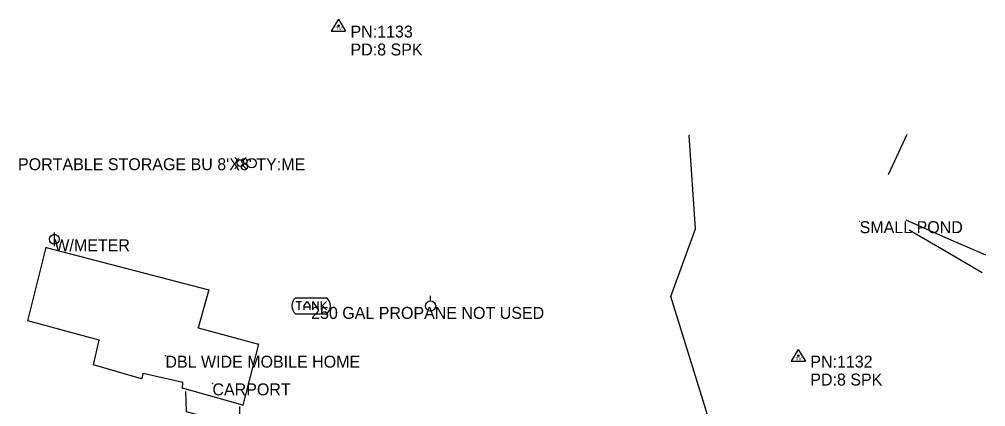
# Model space of a CAD drawing. Extents: x 878399 to 889864, y 1564003 to 1567413.
# Drawn here: x 886066 to 886469.7, y 1564707.5 to 1564869.4 of the extents above; entities that cross this region are included whole.
import ezdxf

# ---------------------------------------------------------------- set-up
doc = ezdxf.new("R2010")
doc.units = 0
for name, color, linetype in [('S_BUILDING', 7, 'Continuous'), ('S_DITCHLINE', 7, 'Continuous'), ('S_EDGE_BITUMINOUS', 7, 'Continuous'), ('S_FENCE', 7, 'Continuous'), ('S_MSC_PT_SYM', 7, 'Continuous'), ('S_SECONDARY_CTL', 7, 'Continuous'), ('S_SECONDARY_CTL_ANNOT', 7, 'Continuous'), ('S_STR_PT_SYM', 7, 'Continuous'), ('S_SURVEY_TEXT_ANNOT', 7, 'Continuous'), ('S_TANK', 7, 'Continuous'), ('S_TANK_ANNOT', 7, 'Continuous'), ('S_UTILITY_POLE', 7, 'Continuous'), ('S_UTILITY_POLE_ANNOT', 7, 'Continuous')]:
    doc.layers.add(name, color=color, linetype=linetype)

msp = doc.modelspace()

# ---------------------------------------------------------------- linework, layer by layer
at = {"layer": 'S_BUILDING'}
for p, q in [((886069.58, 1564743.36), (886077.3, 1564774.11)), ((886077.3, 1564774.11), (886145.13, 1564756.32)), ((886145.13, 1564756.32), (886140.72, 1564740.53)), ((886099.45, 1564735.27), (886069.58, 1564743.36)), ((886140.72, 1564740.53), (886165.87, 1564733.62)), ((886097.06, 1564725.06), (886099.45, 1564735.27)), ((886165.87, 1564733.62), (886159.4, 1564708.12)), ((886117.05, 1564719.16), (886097.06, 1564725.06)), ((886117.77, 1564721.44), (886117.05, 1564719.16)), ((886134.3, 1564717.64), (886117.77, 1564721.44)), ((886134.22, 1564715.25), (886134.3, 1564717.64)), ((886159.4, 1564708.12), (886134.22, 1564715.25))]:
    msp.add_line(p, q, dxfattribs=at)
at = {"layer": 'S_DITCHLINE'}
for points in [[(886436.81, 1564821.26), (886428.95, 1564804.48)], [(886469.69, 1564770.81), (886453.05, 1564778.16), (886436.42, 1564785.51)], [(886468.22, 1564763.5), (886453.01, 1564772.37), (886437.79, 1564781.25)]]:
    msp.add_lwpolyline(points, dxfattribs=at)
at = {"layer": 'S_EDGE_BITUMINOUS'}
msp.add_lwpolyline([(886135.38, 1564713.85), (886135.68, 1564705.53), (886158.05, 1564699.54), (886158.15, 1564707.53)], dxfattribs=at)
at = {"layer": 'S_FENCE'}
for p, q in [((886348.44, 1564781.84), (886345.77, 1564820.82)), ((886338.23, 1564753.54), (886348.44, 1564781.84)), ((886360.27, 1564682.48), (886338.23, 1564753.54))]:
    msp.add_line(p, q, dxfattribs=at)
at = {"layer": 'S_MSC_PT_SYM'}
for points in [[(886345.77, 1564820.82), (886345.77, 1564820.87), (886345.77, 1564820.82), (886345.72, 1564820.82), (886345.77, 1564820.82), (886345.77, 1564820.77), (886345.77, 1564820.82), (886345.82, 1564820.82)], [(886348.44, 1564781.84), (886348.44, 1564781.89), (886348.44, 1564781.84), (886348.39, 1564781.84), (886348.44, 1564781.84), (886348.44, 1564781.79), (886348.44, 1564781.84), (886348.49, 1564781.84)], [(886417.03, 1564785.05), (886417.03, 1564785.1), (886417.03, 1564785.05), (886416.98, 1564785.05), (886417.03, 1564785.05), (886417.03, 1564785), (886417.03, 1564785.05), (886417.08, 1564785.05)], [(886338.23, 1564753.54), (886338.23, 1564753.59), (886338.23, 1564753.54), (886338.18, 1564753.54), (886338.23, 1564753.54), (886338.23, 1564753.49), (886338.23, 1564753.54), (886338.28, 1564753.54)], [(886127.05, 1564728.83), (886127.05, 1564728.88), (886127.05, 1564728.83), (886127, 1564728.83), (886127.05, 1564728.83), (886127.05, 1564728.78), (886127.05, 1564728.83), (886127.1, 1564728.83)], [(886146.69, 1564717.25), (886146.69, 1564717.3), (886146.69, 1564717.25), (886146.64, 1564717.25), (886146.69, 1564717.25), (886146.69, 1564717.2), (886146.69, 1564717.25), (886146.74, 1564717.25)]]:
    msp.add_lwpolyline(points, dxfattribs=at)
at = {"layer": 'S_SECONDARY_CTL'}
for p, q in [((886199.37, 1564869.43), (886196.36, 1564864.48)), ((886199.37, 1564869.43), (886202.31, 1564864.48)), ((886196.36, 1564864.48), (886202.31, 1564864.48)), ((886391.43, 1564731.47), (886388.42, 1564726.52)), ((886391.43, 1564731.47), (886394.38, 1564726.52)), ((886388.42, 1564726.52), (886394.38, 1564726.52))]:
    msp.add_line(p, q, dxfattribs=at)
for centre, radius in [((886199.37, 1564866.82), 0.311), ((886199.37, 1564866.82), 0.183), ((886199.37, 1564866.82), 0.103), ((886391.43, 1564728.86), 0.311), ((886391.43, 1564728.86), 0.183), ((886391.43, 1564728.86), 0.103)]:
    msp.add_circle(centre, radius, dxfattribs=at)
at = {"layer": 'S_STR_PT_SYM'}
for points in [[(886077.3, 1564774.11), (886077.3, 1564774.16), (886077.3, 1564774.11), (886077.25, 1564774.11), (886077.3, 1564774.11), (886077.3, 1564774.06), (886077.3, 1564774.11), (886077.35, 1564774.11)], [(886145.13, 1564756.32), (886145.13, 1564756.37), (886145.13, 1564756.32), (886145.08, 1564756.32), (886145.13, 1564756.32), (886145.13, 1564756.27), (886145.13, 1564756.32), (886145.18, 1564756.32)], [(886069.58, 1564743.36), (886069.58, 1564743.41), (886069.58, 1564743.36), (886069.53, 1564743.36), (886069.58, 1564743.36), (886069.58, 1564743.31), (886069.58, 1564743.36), (886069.63, 1564743.36)], [(886140.72, 1564740.53), (886140.72, 1564740.58), (886140.72, 1564740.53), (886140.67, 1564740.53), (886140.72, 1564740.53), (886140.72, 1564740.48), (886140.72, 1564740.53), (886140.77, 1564740.53)], [(886099.45, 1564735.27), (886099.45, 1564735.32), (886099.45, 1564735.27), (886099.4, 1564735.27), (886099.45, 1564735.27), (886099.45, 1564735.22), (886099.45, 1564735.27), (886099.5, 1564735.27)], [(886165.87, 1564733.62), (886165.87, 1564733.67), (886165.87, 1564733.62), (886165.82, 1564733.62), (886165.87, 1564733.62), (886165.87, 1564733.57), (886165.87, 1564733.62), (886165.92, 1564733.62)], [(886097.06, 1564725.06), (886097.06, 1564725.11), (886097.06, 1564725.06), (886097.01, 1564725.06), (886097.06, 1564725.06), (886097.06, 1564725.01), (886097.06, 1564725.06), (886097.11, 1564725.06)], [(886117.77, 1564721.44), (886117.77, 1564721.49), (886117.77, 1564721.44), (886117.72, 1564721.44), (886117.77, 1564721.44), (886117.77, 1564721.39), (886117.77, 1564721.44), (886117.82, 1564721.44)], [(886117.05, 1564719.16), (886117.05, 1564719.21), (886117.05, 1564719.16), (886117, 1564719.16), (886117.05, 1564719.16), (886117.05, 1564719.11), (886117.05, 1564719.16), (886117.1, 1564719.16)], [(886134.3, 1564717.64), (886134.3, 1564717.69), (886134.3, 1564717.64), (886134.25, 1564717.64), (886134.3, 1564717.64), (886134.3, 1564717.59), (886134.3, 1564717.64), (886134.35, 1564717.64)], [(886134.22, 1564715.25), (886134.22, 1564715.3), (886134.22, 1564715.25), (886134.17, 1564715.25), (886134.22, 1564715.25), (886134.22, 1564715.2), (886134.22, 1564715.25), (886134.27, 1564715.25)], [(886159.4, 1564708.12), (886159.4, 1564708.17), (886159.4, 1564708.12), (886159.35, 1564708.12), (886159.4, 1564708.12), (886159.4, 1564708.07), (886159.4, 1564708.12), (886159.45, 1564708.12)]]:
    msp.add_lwpolyline(points, dxfattribs=at)
at = {"layer": 'S_TANK'}
for p, q in [((886181.34, 1564753.03), (886194.45, 1564753.03)), ((886181.59, 1564751.54), (886183.86, 1564751.54)), ((886182.76, 1564751.54), (886182.76, 1564748.05)), ((886185.08, 1564749.8), (886186.24, 1564751.54)), ((886185.08, 1564748.05), (886185.08, 1564749.8)), ((886187.34, 1564749.15), (886185.08, 1564749.15)), ((886186.24, 1564751.54), (886187.34, 1564749.8)), ((886187.34, 1564749.8), (886187.34, 1564748.05)), ((886188.57, 1564748.05), (886188.57, 1564751.54)), ((886188.57, 1564751.54), (886190.83, 1564748.05)), ((886190.83, 1564748.05), (886190.83, 1564751.54)), ((886192.06, 1564751.54), (886192.06, 1564748.05)), ((886192.06, 1564749.22), (886194.32, 1564751.54)), ((886192.64, 1564749.73), (886194.32, 1564748.05)), ((886181.34, 1564746.38), (886194.45, 1564746.38))]:
    msp.add_line(p, q, dxfattribs=at)
for centre, radius, start, end in [((886184.52, 1564749.7), 4.6, 133.7339, 226.2661), ((886191.66, 1564749.7), 4.34, 309.9965, 50.0035)]:
    msp.add_arc(centre, radius, start, end, dxfattribs=at)
at = {"layer": 'S_UTILITY_POLE'}
for p, q in [((886157.39, 1564810.33), (886156.02, 1564811.69)), ((886159.41, 1564810.33), (886160.78, 1564811.69)), ((886156.02, 1564806.94), (886157.39, 1564808.31)), ((886160.78, 1564806.94), (886159.41, 1564808.31)), ((886159.83, 1564809.32), (886161.05, 1564809.32)), ((886080.66, 1564774.59), (886080.66, 1564780.38)), ((886237.72, 1564751.75), (886237.72, 1564753.86))]:
    msp.add_line(p, q, dxfattribs=at)
for centre, radius in [((886158.4, 1564809.32), 1.43), ((886163.05, 1564809.32), 2), ((886080.66, 1564777.52), 2.05), ((886237.84, 1564749.61), 2.13)]:
    msp.add_circle(centre, radius, dxfattribs=at)

# ---------------------------------------------------------------- texts
at = {"layer": 'S_SECONDARY_CTL'}
for p in [(886198.16, 1564864.81), (886390.23, 1564726.85)]:
    msp.add_text('TV', height=1.5, rotation=360, dxfattribs=at).set_placement(p)
at = {"layer": 'S_SECONDARY_CTL_ANNOT'}
for s, p in [('PN:1133', (886204.37, 1564861.82)), ('PD:8 SPK', (886204.37, 1564854.32)), ('PN:1132', (886396.43, 1564723.86)), ('PD:8 SPK', (886396.43, 1564716.36))]:
    msp.add_text(s, height=5, dxfattribs=at).set_placement(p)
at = {"layer": 'S_SURVEY_TEXT_ANNOT'}
for s, p in [("PORTABLE STORAGE BU 8'X8' TY:ME", (886065.49, 1564806.37)), ('SMALL POND', (886417.03, 1564780.05)), ('DBL WIDE MOBILE HOME', (886127.05, 1564723.83)), ('CARPORT', (886146.69, 1564712.25))]:
    msp.add_text(s, height=5, dxfattribs=at).set_placement(p)
at = {"layer": 'S_TANK_ANNOT'}
msp.add_text('250 GAL PROPANE NOT USED', height=5, dxfattribs=at).set_placement((886187.92, 1564744.22))
at = {"layer": 'S_UTILITY_POLE_ANNOT'}
msp.add_text('W/METER', height=5, dxfattribs=at).set_placement((886080.66, 1564772.52))

doc.saveas('drawing.dxf')
